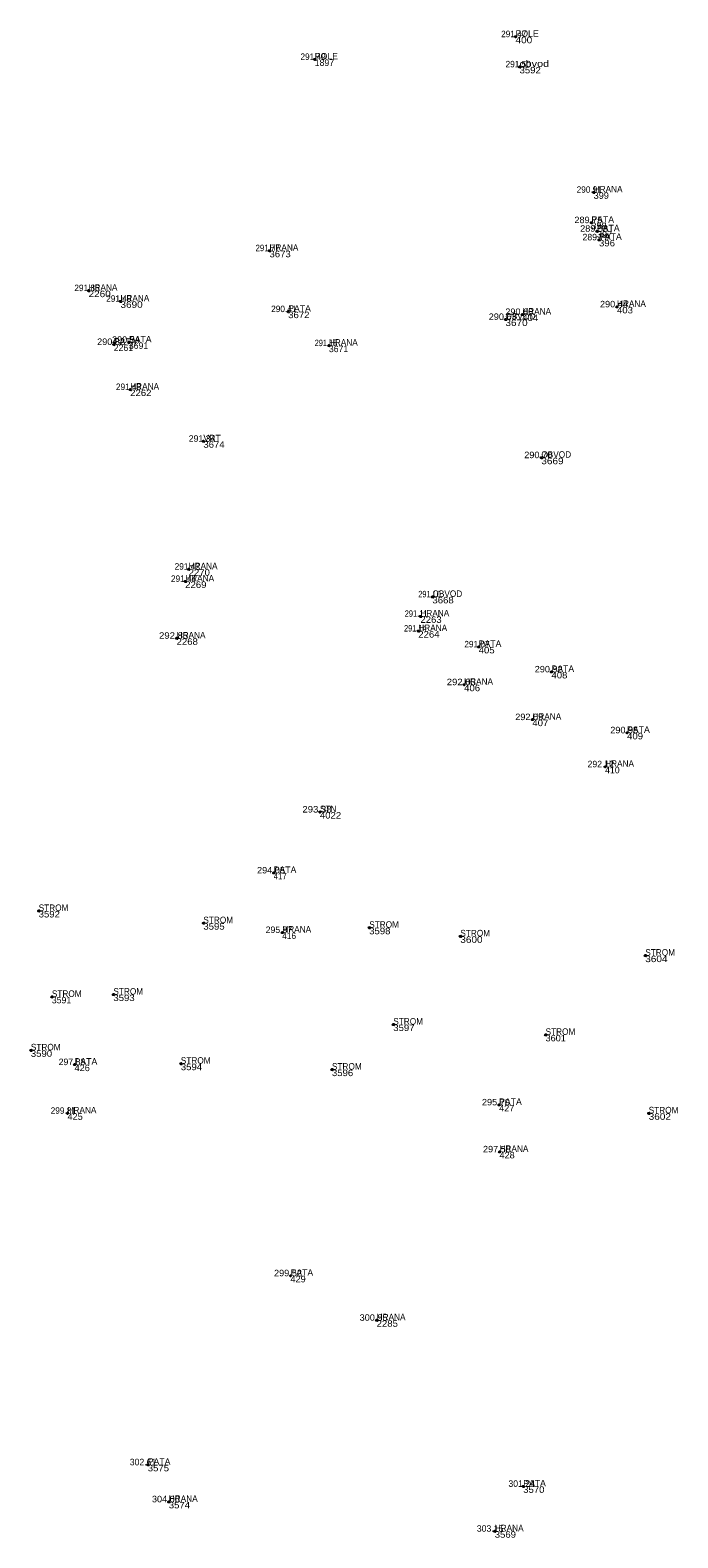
# Model space of a CAD drawing. Extents: x -565336 to -561834, y -1146819 to -1145270.
# Drawn here: x -563836.8 to -563802.9, y -1145852.7 to -1145773.8 of the extents above; entities that cross this region are included whole.
import ezdxf
from ezdxf.enums import TextEntityAlignment as Align

# ---------------------------------------------------------------- set-up
doc = ezdxf.new("R2010")
doc.units = 0
doc.header["$LTSCALE"] = 0.14
doc.header["$PDMODE"] = 32
doc.header["$PDSIZE"] = 0.07
for name, color, linetype in [('40', 7, 'Continuous'), ('43', 7, 'Continuous'), ('44', 7, 'Continuous'), ('45', 7, 'Continuous')]:
    doc.layers.add(name, color=color, linetype=linetype)

msp = doc.modelspace()

# ---------------------------------------------------------------- linework, layer by layer
at = {"layer": '40'}
for p in [(-563811.43, -1145774.1), (-563821.94, -1145775.29), (-563811.22, -1145775.68), (-563807.34, -1145782.25), (-563807.46, -1145783.84), (-563807.17, -1145784.29), (-563807.06, -1145784.74), (-563824.31, -1145785.31), (-563833.78, -1145787.4), (-563832.11, -1145787.96), (-563806.12, -1145788.25), (-563823.33, -1145788.5), (-563811.96, -1145788.91), (-563811.08, -1145788.65), (-563832.46, -1145790.22), (-563831.67, -1145790.11), (-563821.2, -1145790.28), (-563831.6, -1145792.58), (-563827.77, -1145795.29), (-563810.08, -1145796.15), (-563828.72, -1145802.63), (-563828.54, -1145801.99), (-563815.78, -1145803.44), (-563816.41, -1145804.46), (-563829.17, -1145805.61), (-563816.52, -1145805.23), (-563813.36, -1145806.06), (-563809.55, -1145807.37), (-563814.12, -1145808.04), (-563810.55, -1145809.87), (-563805.59, -1145810.56), (-563806.74, -1145812.34), (-563821.67, -1145814.71), (-563824.09, -1145817.9), (-563836.39, -1145819.89), (-563827.77, -1145820.53), (-563819.09, -1145820.77), (-563823.64, -1145821.02), (-563814.32, -1145821.22), (-563804.64, -1145822.23), (-563835.7, -1145824.39), (-563832.48, -1145824.27), (-563817.83, -1145825.84), (-563809.86, -1145826.38), (-563836.8, -1145827.19), (-563828.95, -1145827.89), (-563834.51, -1145827.94), (-563821.04, -1145828.2), (-563812.29, -1145830.05), (-563834.88, -1145830.49), (-563804.46, -1145830.49), (-563812.27, -1145832.51), (-563823.21, -1145839), (-563818.7, -1145841.33), (-563830.68, -1145848.9), (-563811.03, -1145850.03), (-563829.58, -1145850.84), (-563812.52, -1145852.38)]:
    msp.add_point(p, dxfattribs=at)

# ---------------------------------------------------------------- texts
at = {"layer": '43'}
for s, width, p in [('400', 1.15, (-563811.43, -1145774.44)), ('3592', 1.1, (-563811.22, -1145776.02)), ('399', 1.05, (-563807.34, -1145782.59)), ('398', 1.05, (-563807.46, -1145784.18)), ('397', 1.05, (-563807.17, -1145784.63)), ('396', 1.1, (-563807.06, -1145785.08)), ('3673', 1.1, (-563824.31, -1145785.65)), ('2260', 1.15, (-563833.78, -1145787.74)), ('3690', 1.15, (-563832.11, -1145788.3)), ('403', 1.1, (-563806.12, -1145788.59)), ('3672', 1.1, (-563823.33, -1145788.84)), ('3670', 1.15, (-563811.96, -1145789.25)), ('404', 1.1, (-563811.08, -1145788.99)), ('2262', 1.1, (-563831.6, -1145792.92)), ('3674', 1.1, (-563827.77, -1145795.63)), ('3669', 1.15, (-563810.08, -1145796.49)), ('2270', 1.1, (-563828.54, -1145802.33)), ('2269', 1.1, (-563828.72, -1145802.97)), ('3668', 1.1, (-563815.78, -1145803.78)), ('2263', 1.1, (-563816.41, -1145804.8)), ('2268', 1.1, (-563829.17, -1145805.95)), ('2264', 1.1, (-563816.52, -1145805.57)), ('405', 1.1, (-563813.36, -1145806.4)), ('406', 1.1, (-563814.12, -1145808.38)), ('408', 1.1, (-563809.55, -1145807.71)), ('407', 1.1, (-563810.55, -1145810.21)), ('409', 1.1, (-563805.59, -1145810.9)), ('4022', 1.1, (-563821.67, -1145815.05)), ('417', 0.9, (-563824.09, -1145818.24)), ('3592', 1.1, (-563836.39, -1145820.23)), ('3595', 1.1, (-563827.77, -1145820.87)), ('3598', 1.1, (-563819.09, -1145821.11)), ('416', 0.95, (-563823.64, -1145821.36)), ('3600', 1.15, (-563814.32, -1145821.56)), ('3604', 1.15, (-563804.64, -1145822.57)), ('3593', 1.1, (-563832.48, -1145824.61)), ('3597', 1.1, (-563817.83, -1145826.18)), ('3601', 1.05, (-563809.86, -1145826.72)), ('3590', 1.1, (-563836.8, -1145827.53)), ('426', 1.05, (-563834.51, -1145828.28)), ('3594', 1.1, (-563828.95, -1145828.23)), ('3596', 1.1, (-563821.04, -1145828.54)), ('427', 1.05, (-563812.29, -1145830.39)), ('425', 1.05, (-563834.88, -1145830.83)), ('3602', 1.15, (-563804.46, -1145830.83)), ('428', 1.05, (-563812.27, -1145832.85)), ('429', 1.05, (-563823.21, -1145839.34)), ('2285', 1.1, (-563818.7, -1145841.67)), ('3575', 1.1, (-563830.68, -1145849.24)), ('3570', 1.1, (-563811.03, -1145850.37)), ('3574', 1.1, (-563829.58, -1145851.18)), ('3569', 1.1, (-563812.52, -1145852.72))]:
    msp.add_text(s, height=0.34, dxfattribs=dict(at, width=width)).set_placement(p)
for s, p in [('1897', (-563821.94, -1145775.63)), ('2261', (-563832.46, -1145790.56)), ('3691', (-563831.67, -1145790.45)), ('3671', (-563821.2, -1145790.62)), ('410', (-563806.74, -1145812.68)), ('3591', (-563835.7, -1145824.73))]:
    msp.add_text(s, height=0.34, dxfattribs=at).set_placement(p)
at = {"layer": '44'}
for s, width, p in [('291.47', 0.95, (-563811.524, -1145774.124)), ('291.49', 0.95, (-563822.0255, -1145775.314)), ('291.50', 0.95, (-563811.291, -1145775.704)), ('290.91', 0.95, (-563807.5705, -1145782.274)), ('289.75', 1.05, (-563807.6195, -1145783.864)), ('289.58', 1.05, (-563807.3175, -1145784.314)), ('291.77', 0.9, (-563824.412, -1145785.334)), ('291.86', 0.95, (-563833.8605, -1145787.424)), ('291.49', 0.95, (-563832.1955, -1145787.984)), ('290.41', 0.95, (-563823.5605, -1145788.524)), ('290.60', 1.05, (-563811.2355, -1145788.674)), ('290.44', 1.05, (-563806.2805, -1145788.274)), ('290.63', 1.05, (-563812.1035, -1145788.934)), ('290.82', 1.05, (-563832.6005, -1145790.244)), ('290.54', 1.05, (-563831.8215, -1145790.134)), ('291.18', 0.85, (-563821.3515, -1145790.304)), ('291.49', 0.95, (-563831.6855, -1145792.604)), ('290.70', 1.05, (-563810.2435, -1145796.174)), ('291.42', 0.95, (-563828.611, -1145802.014)), ('291.44', 0.95, (-563828.8055, -1145802.654)), ('291.10', 0.85, (-563815.93, -1145803.464)), ('291.11', 0.75, (-563816.635, -1145804.484)), ('291.14', 0.85, (-563816.6755, -1145805.254)), ('292.85', 1.1, (-563829.3255, -1145805.634)), ('291.07', 0.95, (-563813.4485, -1145806.084)), ('290.92', 1.05, (-563809.696, -1145807.394)), ('292.03', 1.1, (-563814.2675, -1145808.064)), ('292.09', 1.05, (-563810.715, -1145809.894)), ('290.95', 1.05, (-563805.7415, -1145810.584)), ('293.38', 1.1, (-563821.8215, -1145814.734)), ('294.05', 1.05, (-563824.2305, -1145817.924)), ('299.81', 0.95, (-563835.0995, -1145830.514)), ('295.70', 1.05, (-563812.4575, -1145830.074)), ('297.58', 1.05, (-563812.404, -1145832.534)), ('299.52', 1.05, (-563823.341, -1145839.024)), ('300.95', 1.05, (-563818.8595, -1145841.354)), ('304.00', 1.05, (-563829.7325, -1145850.864))]:
    msp.add_text(s, height=0.34, dxfattribs=dict(at, width=width)).set_placement(p, align=Align.CENTER)
for s, p in [('289.79', (-563807.229, -1145784.764)), ('291.34', (-563827.8385, -1145795.314)), ('292.12', (-563806.965, -1145812.364)), ('295.97', (-563823.813, -1145821.044)), ('297.88', (-563834.648, -1145827.964)), ('302.61', (-563830.928, -1145848.924)), ('301.24', (-563811.109, -1145850.054)), ('303.15', (-563812.761, -1145852.404))]:
    msp.add_text(s, height=0.34, dxfattribs=at).set_placement(p, align=Align.CENTER)
at = {"layer": '45'}
for s, p in [('POLE', (-563811.43, -1145774.1)), ('POLE', (-563821.94, -1145775.29)), ('PATA', (-563807.46, -1145783.84)), ('PATA', (-563807.17, -1145784.29)), ('PATA', (-563807.06, -1145784.74)), ('PATA', (-563823.33, -1145788.5)), ('PATA', (-563832.46, -1145790.22)), ('PATA', (-563831.67, -1145790.11)), ('VRT', (-563827.77, -1145795.29)), ('PATA', (-563813.36, -1145806.06)), ('PATA', (-563809.55, -1145807.37)), ('PATA', (-563805.59, -1145810.56)), ('PATA', (-563824.09, -1145817.9)), ('PATA', (-563834.51, -1145827.94)), ('PATA', (-563812.29, -1145830.05)), ('PATA', (-563823.21, -1145839)), ('PATA', (-563830.68, -1145848.9)), ('PATA', (-563811.03, -1145850.03))]:
    msp.add_text(s, height=0.34, dxfattribs=at).set_placement(p)
for s, width, p in [('obvod', 1.25, (-563811.22, -1145775.68)), ('HRANA', 0.95, (-563807.34, -1145782.25)), ('HRANA', 0.95, (-563824.31, -1145785.31)), ('HRANA', 0.95, (-563833.78, -1145787.4)), ('HRANA', 0.95, (-563832.11, -1145787.96)), ('HRANA', 0.95, (-563811.08, -1145788.65)), ('HRANA', 0.95, (-563806.12, -1145788.25)), ('OBVOD', 0.95, (-563811.96, -1145788.91)), ('HRANA', 0.95, (-563821.2, -1145790.28)), ('HRANA', 0.95, (-563831.6, -1145792.58)), ('OBVOD', 0.95, (-563810.08, -1145796.15)), ('HRANA', 0.95, (-563828.54, -1145801.99)), ('HRANA', 0.95, (-563828.72, -1145802.63)), ('OBVOD', 0.95, (-563815.78, -1145803.44)), ('HRANA', 0.95, (-563816.41, -1145804.46)), ('HRANA', 0.95, (-563816.52, -1145805.23)), ('HRANA', 0.95, (-563829.17, -1145805.61)), ('HRANA', 0.95, (-563814.12, -1145808.04)), ('HRANA', 0.95, (-563810.55, -1145809.87)), ('HRANA', 0.95, (-563806.74, -1145812.34)), ('STN', 0.95, (-563821.67, -1145814.71)), ('STROM', 0.95, (-563836.39, -1145819.89)), ('STROM', 0.95, (-563827.77, -1145820.53)), ('HRANA', 0.95, (-563823.64, -1145821.02)), ('STROM', 0.95, (-563819.09, -1145820.77)), ('STROM', 0.95, (-563814.32, -1145821.22)), ('STROM', 0.95, (-563804.64, -1145822.23)), ('STROM', 0.95, (-563832.48, -1145824.27)), ('STROM', 0.95, (-563835.7, -1145824.39)), ('STROM', 0.95, (-563817.83, -1145825.84)), ('STROM', 0.95, (-563809.86, -1145826.38)), ('STROM', 0.95, (-563836.8, -1145827.19)), ('STROM', 0.95, (-563828.95, -1145827.89)), ('STROM', 0.95, (-563821.04, -1145828.2)), ('HRANA', 0.95, (-563834.88, -1145830.49)), ('STROM', 0.95, (-563804.46, -1145830.49)), ('HRANA', 0.95, (-563812.27, -1145832.51)), ('HRANA', 0.95, (-563818.7, -1145841.33)), ('HRANA', 0.95, (-563829.58, -1145850.84)), ('HRANA', 0.95, (-563812.52, -1145852.38))]:
    msp.add_text(s, height=0.34, dxfattribs=dict(at, width=width)).set_placement(p)

doc.saveas('drawing.dxf')
